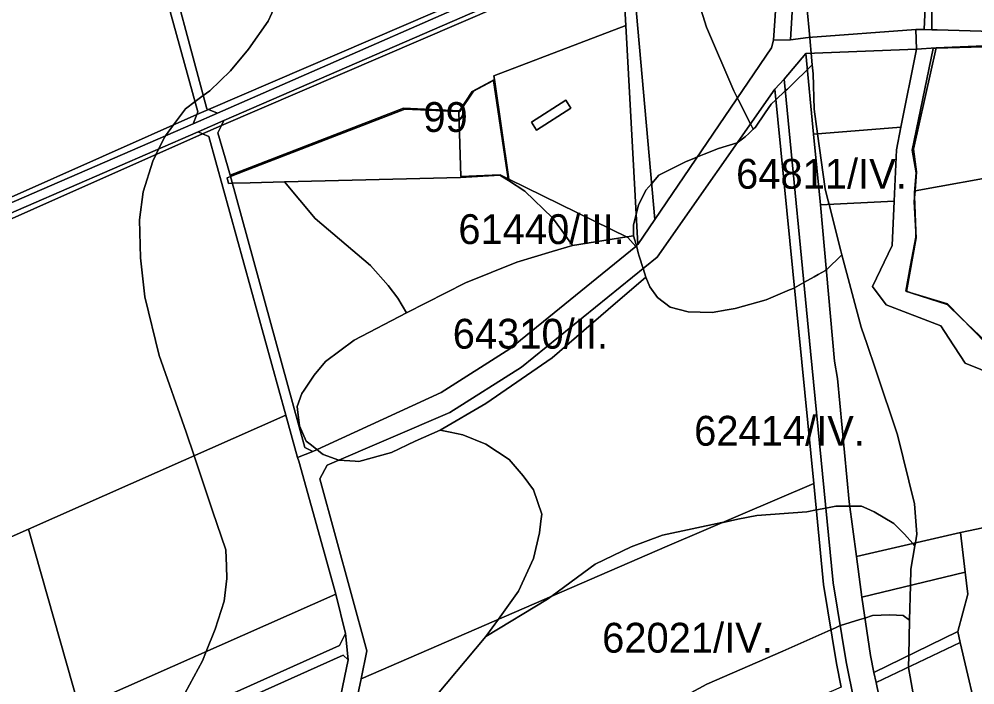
# Model space of a CAD drawing. Extents: x -522079 to -518792, y -1142400 to -1139961.
# Drawn here: x -520985.3 to -520504.8, y -1141508 to -1141173.1 of the extents above; entities that cross this region are included whole.
import ezdxf

# ---------------------------------------------------------------- set-up
doc = ezdxf.new("R2010")
doc.units = 0
for name, color, linetype in [('Bonity', 7, 'Continuous'), ('Hranice parcel', 7, 'Continuous'), ('Parcelní čísla', 7, 'Continuous'), ('Poz předměty', 7, 'Continuous'), ('Vnitřní kresba', 7, 'Continuous'), ('Značky bodu BP', 7, 'Continuous'), ('Značky budov', 7, 'Continuous')]:
    doc.layers.add(name, color=color, linetype=linetype)

msp = doc.modelspace()

# ---------------------------------------------------------------- linework, layer by layer
at = {"layer": 'Bonity'}
msp.add_lwpolyline([(-520879.25, -1141251.61), (-520880.53, -1141246.97), (-520885.33, -1141230.38), (-520883.56, -1141226.59), (-520683.09, -1141140.3), (-520681.18, -1141161.32), (-520680.34, -1141176.38), (-520746.65, -1141201.66), (-520746.38, -1141203.48), (-520757.5, -1141209.45), (-520763.86, -1141219.18), (-520792.12, -1141217.97)], close=True, dxfattribs=at)
at = {"layer": 'Hranice parcel'}
for points in [[(-521027.41, -1141281.92), (-520897.83, -1141225.78), (-520885.55, -1141220.5), (-520708.05, -1141142.54), (-520688.68, -1141134.03), (-520675.02, -1141128.07), (-520610.52, -1141099.9), (-520605.48, -1141096), (-520603.47, -1141094.45), (-520599.33, -1141085.41), (-520601.54, -1141117.64), (-520612.8, -1141110.04), (-520615.64, -1141108.13), (-520683.34, -1141137.56), (-520705.75, -1141147.3), (-520882.39, -1141224.1), (-520895.38, -1141229.74), (-521025.25, -1141286.2)], [(-520594.25, -1141129.86), (-520597.46, -1141183.55), (-520606.07, -1141183.78), (-520601.54, -1141117.64)], [(-520847.36, -1141628.04), (-520819.82, -1141495.44), (-520821.3, -1141482.16), (-520826.14, -1141462.3), (-520844.73, -1141395.54), (-520845.27, -1141393.64), (-520837.57, -1141390.54), (-520773.04, -1141360.9), (-520738.6, -1141338.95), (-520675.31, -1141287.41), (-520674.18, -1141286.49), (-520665.65, -1141273.94), (-520607.02, -1141187.64), (-520606.07, -1141183.78), (-520597.46, -1141183.55), (-520588.63, -1141182.42), (-520534.49, -1141178.34), (-520534.17, -1141188.18), (-520589.77, -1141190.43), (-520600.66, -1141203.4), (-520605.35, -1141208.42), (-520664.52, -1141292.81), (-520732.72, -1141348.25), (-520768.7, -1141371.01), (-520830.45, -1141397.51), (-520834.09, -1141404.31), (-520810.51, -1141490.93), (-520813.35, -1141504.9), (-520838.97, -1141624.77)], [(-520500.08, -1141186.63), (-520524.27, -1141187.6), (-520534.17, -1141188.18), (-520534.49, -1141178.34), (-520530.26, -1141178.39), (-520526.48, -1141178.44), (-520523.78, -1141178.47), (-520440.68, -1141181.04)], [(-520572, -1141509.22), (-520574.39, -1141497.17), (-520580.93, -1141457.51), (-520585.72, -1141406.64), (-520605.35, -1141208.42), (-520600.66, -1141203.4), (-520587.35, -1141340.09), (-520576, -1141456.7), (-520569.46, -1141496.36), (-520561.68, -1141535.49)]]:
    msp.add_lwpolyline(points, dxfattribs=at)
for points in [[(-520890.16, -1141218.54), (-520727.16, -1141148.38), (-520686.99, -1141131.09), (-520688.68, -1141134.03), (-520708.05, -1141142.54), (-520885.55, -1141220.5)], [(-520683.34, -1141137.56), (-520683.09, -1141140.3), (-520883.56, -1141226.59), (-520882.39, -1141224.1), (-520705.75, -1141147.3)], [(-520683.09, -1141140.3), (-520677.78, -1141138.02), (-520665.65, -1141273.94), (-520674.18, -1141286.49), (-520680.34, -1141176.38), (-520681.18, -1141161.32)], [(-520535.7, -1141238.47), (-520524.27, -1141187.6), (-520500.08, -1141186.63), (-520488.31, -1141251.1), (-520534.84, -1141259.42), (-520534.05, -1141249.88)], [(-520743.39, -1141251.48), (-520763.26, -1141252.34), (-520764.2, -1141219.7), (-520763.86, -1141219.18), (-520757.5, -1141209.45), (-520746.38, -1141203.48), (-520739.03, -1141253.62)], [(-520727.76, -1141224.94), (-520710.51, -1141213.9), (-520707.92, -1141217.98), (-520725.18, -1141228.99)], [(-520895.96, -1141221.04), (-520890.16, -1141218.54), (-520885.55, -1141220.5), (-520897.83, -1141225.78)], [(-520895.96, -1141221.04), (-520897.83, -1141225.78), (-521027.41, -1141281.92), (-521037.84, -1141286.59), (-521038.45, -1141284.46)], [(-520882.39, -1141224.1), (-520883.56, -1141226.59), (-520893.13, -1141230.74), (-520895.38, -1141229.74)], [(-520837.57, -1141390.54), (-520845.27, -1141393.64), (-520851.22, -1141372.34), (-520889.86, -1141232.13), (-520893.13, -1141230.74), (-520883.56, -1141226.59), (-520885.33, -1141230.38), (-520880.53, -1141246.97), (-520879.25, -1141251.61), (-520841.7, -1141388.53)], [(-520893.13, -1141230.74), (-521147.68, -1141344.03), (-521146.08, -1141340.6), (-521025.25, -1141286.2), (-520895.38, -1141229.74)]]:
    msp.add_lwpolyline(points, close=True, dxfattribs=at)
at = {"layer": 'Parcelní čísla'}
for points in [[(-520948.18, -1141008.97), (-520939.75, -1141038.42), (-520928.14, -1141079.25), (-520914.59, -1141129.89), (-520890.98, -1141218.17), (-520890.16, -1141218.54), (-520895.96, -1141221.04), (-520895.4, -1141219.71), (-520927.66, -1141102.94), (-520964.29, -1140970.32), (-520970.5, -1140967.09), (-520956.56, -1140961.79), (-520959.78, -1140968.46), (-520955.5, -1140983.4), (-520952.2, -1140994.93)], [(-520895.4, -1141219.71), (-520895.96, -1141221.04), (-521038.45, -1141284.46), (-521072.62, -1141164.33), (-521112.83, -1141022.98), (-521082.18, -1141009.47), (-521026.59, -1140987.63), (-520970.5, -1140967.09), (-520964.29, -1140970.32), (-520927.66, -1141102.94)], [(-520914.59, -1141129.89), (-520847.24, -1141100.33), (-520846.14, -1141104.23), (-520733.88, -1141082.24), (-520727.16, -1141148.38), (-520890.16, -1141218.54), (-520890.98, -1141218.17)], [(-520851.22, -1141372.34), (-520980.65, -1141429.68), (-521109.72, -1141486.85), (-521149.23, -1141347.36), (-521147.68, -1141344.03), (-520893.13, -1141230.74), (-520889.86, -1141232.13)], [(-520980.65, -1141429.68), (-520851.22, -1141372.34), (-520845.27, -1141393.64), (-520844.73, -1141395.54), (-520826.14, -1141462.3), (-520955.18, -1141519.6)], [(-520659.49, -1141438.15), (-520585.72, -1141406.64), (-520580.93, -1141457.51), (-520574.39, -1141497.17), (-520572, -1141509.22), (-520635.55, -1141536.73), (-520726.9, -1141576.27), (-520838.97, -1141624.77), (-520813.35, -1141504.9)], [(-520980.65, -1141429.68), (-520955.18, -1141519.6), (-521084.21, -1141576.91), (-521109.72, -1141486.85)], [(-520821.3, -1141482.16), (-520824.28, -1141488.21), (-520974.97, -1141555.99), (-521072.78, -1141598.79), (-521078.78, -1141596.05), (-521084.21, -1141576.91), (-520955.18, -1141519.6), (-520826.14, -1141462.3)], [(-520819.82, -1141495.44), (-520822.47, -1141493.04), (-520972.97, -1141560.63), (-521070.28, -1141603.2), (-521076.03, -1141605.72), (-521077.42, -1141600.82), (-521072.78, -1141598.79), (-520974.97, -1141555.99), (-520824.28, -1141488.21), (-520821.3, -1141482.16)], [(-520822.47, -1141493.04), (-520819.82, -1141495.44), (-520847.36, -1141628.04), (-520954.68, -1141675.43), (-521044.98, -1141715.3), (-521058.67, -1141667), (-521074.66, -1141610.52), (-521070.28, -1141603.2), (-520972.97, -1141560.63)]]:
    msp.add_lwpolyline(points, close=True, dxfattribs=at)
at = {"layer": 'Poz předměty'}
for points in [[(-520597.46, -1141183.55), (-520594.25, -1141129.86), (-520552.98, -1141119.42), (-520553, -1141122.43), (-520562.26, -1141141.67), (-520551.87, -1141154.33), (-520536.94, -1141152.14), (-520531.44, -1141160.96), (-520529.73, -1141167.05), (-520530.26, -1141178.39), (-520534.49, -1141178.34), (-520588.63, -1141182.42)], [(-520432.59, -1141179.7), (-520440.68, -1141181.04), (-520523.78, -1141178.47), (-520526.48, -1141178.44), (-520526.38, -1141166.45), (-520421.91, -1141158.52), (-520408.18, -1141157.48), (-520425.27, -1141175.41)], [(-520679.28, -1141282.96), (-520739.03, -1141253.62), (-520746.38, -1141203.48), (-520746.65, -1141201.66), (-520680.34, -1141176.38), (-520674.18, -1141286.49), (-520675.31, -1141287.41)], [(-520589.77, -1141190.43), (-520534.17, -1141188.18), (-520541.94, -1141227.47), (-520585.84, -1141231.02)], [(-520727.76, -1141224.94), (-520725.18, -1141228.99), (-520707.92, -1141217.98), (-520710.51, -1141213.9)], [(-520585.84, -1141231.02), (-520541.94, -1141227.47), (-520544.19, -1141238.83), (-520545.37, -1141264.63), (-520582.4, -1141266.58)], [(-520534.35, -1141283.17), (-520535.3, -1141264.93), (-520534.84, -1141259.42), (-520488.31, -1141251.1), (-520469.72, -1141352.88), (-520465.21, -1141361), (-520463.1, -1141373.93), (-520471.76, -1141351.9), (-520499.06, -1141336.21), (-520518.61, -1141316.36), (-520539.2, -1141310.09)], [(-520474.23, -1141423.42), (-520512.06, -1141431.3), (-520564.35, -1141443.41), (-520567.96, -1141415.92), (-520573.91, -1141353.97), (-520575.29, -1141345.21), (-520582.4, -1141266.58), (-520545.37, -1141264.63), (-520546.39, -1141287.04), (-520556.25, -1141307.68), (-520549.32, -1141316.76), (-520521.95, -1141327.46), (-520517.94, -1141333.55), (-520509.58, -1141346.13), (-520479.06, -1141358.55)], [(-520509.69, -1141451.35), (-520561.66, -1141463.92), (-520564.35, -1141443.41), (-520512.06, -1141431.3)], [(-520508.38, -1141462.38), (-520513.39, -1141481.08), (-520555.49, -1141501.75), (-520557.24, -1141493.24), (-520561.66, -1141463.92), (-520509.69, -1141451.35)], [(-520513.39, -1141481.08), (-520512.09, -1141486.67), (-520554.45, -1141506.79), (-520555.49, -1141501.75)], [(-520549.23, -1141532.17), (-520554.45, -1141506.79), (-520512.09, -1141486.67), (-520501.99, -1141530.25), (-520478.09, -1141540.57), (-520469.99, -1141514.94), (-520451.9, -1141513.8), (-520438.57, -1141562.32), (-520457.06, -1141558.71), (-520539.75, -1141570.9)]]:
    msp.add_lwpolyline(points, close=True, dxfattribs=at)
msp.add_lwpolyline([(-520561.68, -1141535.49), (-520569.46, -1141496.36), (-520576, -1141456.7), (-520587.35, -1141340.09), (-520600.66, -1141203.4), (-520589.77, -1141190.43), (-520585.84, -1141231.02), (-520582.4, -1141266.58), (-520575.29, -1141345.21), (-520573.91, -1141353.97), (-520567.96, -1141415.92), (-520564.35, -1141443.41), (-520561.66, -1141463.92), (-520557.24, -1141493.24), (-520555.49, -1141501.75), (-520554.45, -1141506.79), (-520549.23, -1141532.17)], dxfattribs=at)
at = {"layer": 'Vnitřní kresba'}
for points in [[(-520526.38, -1141166.45), (-520526.48, -1141178.44), (-520530.26, -1141178.39), (-520529.73, -1141167.05)], [(-520479.06, -1141358.55), (-520509.58, -1141346.13), (-520517.94, -1141333.55), (-520521.95, -1141327.46), (-520549.32, -1141316.76), (-520556.25, -1141307.68), (-520546.39, -1141287.04), (-520545.37, -1141264.63), (-520544.19, -1141238.83), (-520541.94, -1141227.47), (-520534.17, -1141188.18), (-520524.27, -1141187.6), (-520535.7, -1141238.47), (-520534.05, -1141249.88), (-520534.84, -1141259.42), (-520535.3, -1141264.93), (-520534.35, -1141283.17), (-520539.2, -1141310.09), (-520518.61, -1141316.36), (-520499.06, -1141336.21)], [(-520501.99, -1141530.25), (-520512.09, -1141486.67), (-520513.39, -1141481.08), (-520508.38, -1141462.38), (-520509.69, -1141451.35), (-520512.06, -1141431.3), (-520474.23, -1141423.42)]]:
    msp.add_lwpolyline(points, dxfattribs=at)
at = {"layer": 'Značky bodu BP'}
for points in [[(-520906.25, -1141519.97), (-520893.11, -1141495.88), (-520891.25, -1141491.21), (-520886.77, -1141479.98), (-520882.24, -1141465.89), (-520880.88, -1141454.53), (-520881.08, -1141448.32), (-520881.34, -1141439.99), (-520888.13, -1141420.45), (-520897.33, -1141392.76), (-520901.27, -1141380.91), (-520914.86, -1141342.28), (-520922.11, -1141312.75), (-520924.37, -1141293.2), (-520924.82, -1141274.12), (-520923.01, -1141260.03), (-520918.03, -1141244.58), (-520916.34, -1141241.07), (-520915, -1141238.27), (-520912.14, -1141232.31), (-520911.78, -1141231.82), (-520907.65, -1141226.24), (-520901.72, -1141218.22), (-520896.82, -1141214.58), (-520892.75, -1141211.56), (-520889.49, -1141209.13), (-520879.07, -1141199.13), (-520870.01, -1141188.23), (-520860.04, -1141174.14), (-520854.61, -1141161.87)], [(-520854.61, -1141161.87), (-520860.04, -1141174.14), (-520870.01, -1141188.23), (-520879.07, -1141199.13), (-520889.49, -1141209.13), (-520892.75, -1141211.56), (-520896.82, -1141214.58), (-520901.72, -1141218.22), (-520907.65, -1141226.24), (-520911.78, -1141231.82), (-520912.14, -1141232.31), (-520915, -1141238.27), (-520916.34, -1141241.07), (-520918.03, -1141244.58), (-520923.01, -1141260.03), (-520924.82, -1141274.12), (-520924.37, -1141293.2), (-520922.11, -1141312.75), (-520914.86, -1141342.28), (-520901.27, -1141380.91), (-520897.33, -1141392.76), (-520888.13, -1141420.45), (-520881.34, -1141439.99), (-520881.08, -1141448.32), (-520880.88, -1141454.53), (-520882.24, -1141465.89), (-520886.77, -1141479.98), (-520891.25, -1141491.21), (-520893.11, -1141495.88), (-520906.25, -1141519.97)], [(-520644.35, -1141162.05), (-520639.78, -1141177.21), (-520625.97, -1141209.18), (-520624.13, -1141212.83), (-520623.62, -1141213.83), (-520617.56, -1141225.84), (-520616.21, -1141228.52), (-520618.44, -1141230.62), (-520620.26, -1141232.34), (-520624.21, -1141235.31), (-520624.35, -1141235.42), (-520633.7, -1141238.2), (-520640.88, -1141241.06), (-520644.21, -1141242.38), (-520646.99, -1141243.49), (-520649.92, -1141244.66), (-520663.65, -1141251.69), (-520667.27, -1141255.8), (-520670.23, -1141259.17), (-520673.89, -1141266.75), (-520675.03, -1141271.22), (-520676.44, -1141276.73), (-520676.44, -1141282.14), (-520679.84, -1141282.68), (-520707.07, -1141287), (-520712.45, -1141279.5), (-520717.11, -1141273), (-520731.06, -1141259.66), (-520739.34, -1141254.29), (-520739.47, -1141253.4), (-520746.78, -1141204), (-520756.85, -1141209.44), (-520763.8, -1141219.61), (-520764.13, -1141219.59), (-520791.31, -1141218.35), (-520871.38, -1141249.26), (-520879.08, -1141252.24), (-520880.78, -1141252.89), (-520880, -1141255.73), (-520878.14, -1141255.68), (-520869.12, -1141255.45), (-520851.89, -1141255.02), (-520836.39, -1141273.44), (-520808.7, -1141297.06), (-520799.76, -1141307.12), (-520794.96, -1141313.47), (-520790.6, -1141320.91), (-520816.82, -1141334.59), (-520831.31, -1141345.42), (-520837, -1141352.26), (-520842.08, -1141359.69), (-520843.25, -1141361.39), (-520845.52, -1141367.94), (-520845.35, -1141369.42), (-520844.38, -1141377.63), (-520840.97, -1141385.33), (-520838.35, -1141387.44), (-520835.61, -1141389.64), (-520834.78, -1141390.3), (-520833.74, -1141391.13), (-520832.45, -1141392.17), (-520824.58, -1141394.99), (-520824.49, -1141395.02), (-520816.33, -1141395.49), (-520814.55, -1141395.59), (-520798.06, -1141391.03), (-520786.13, -1141385.33), (-520773.63, -1141379.92), (-520768.66, -1141380.95), (-520762.28, -1141382.28), (-520750.59, -1141386.97), (-520738.9, -1141394.59), (-520731.89, -1141402.8), (-520726.63, -1141409.84), (-520722.54, -1141422.15), (-520722.98, -1141425.69), (-520723.7, -1141431.53), (-520726.63, -1141444.43), (-520734.22, -1141460.84), (-520744.32, -1141474.95), (-520750.59, -1141483.71), (-520775.72, -1141513.61)], [(-520589.2, -1141166.56), (-520587.79, -1141182.35), (-520587.59, -1141184.62), (-520587.08, -1141190.32), (-520586.56, -1141196.12), (-520587.8, -1141197.35), (-520588.98, -1141198.53), (-520595.57, -1141205.08), (-520599.04, -1141208.31), (-520599.49, -1141208.72), (-520600.09, -1141209.27), (-520604.83, -1141213.68), (-520607.26, -1141215.93), (-520610.17, -1141220.2), (-520615.14, -1141227.51), (-520616.21, -1141228.52), (-520617.56, -1141225.84), (-520623.62, -1141213.83), (-520624.13, -1141212.83), (-520625.97, -1141209.18), (-520639.78, -1141177.21), (-520644.35, -1141162.05)], [(-520533.32, -1141526.62), (-520538.18, -1141499.21), (-520538.17, -1141499.06), (-520538.02, -1141493.17), (-520537.57, -1141475.45), (-520537.16, -1141457.99), (-520536.96, -1141449.86), (-520534.94, -1141438.08), (-520534.67, -1141436.53), (-520533.93, -1141432.19), (-520535.14, -1141416.96), (-520543.64, -1141382.23), (-520554.4, -1141350.22), (-520559.25, -1141335.8), (-520560.23, -1141332.87), (-520561.86, -1141328.01), (-520571.65, -1141291.62), (-520572.19, -1141289.63), (-520578.1, -1141266.35), (-520579.04, -1141262.66), (-520580.09, -1141258.56), (-520583.85, -1141230.86), (-520585.55, -1141218.35), (-520586.16, -1141200.68), (-520586.56, -1141196.12), (-520587.08, -1141190.32), (-520587.59, -1141184.62), (-520587.79, -1141182.35), (-520589.2, -1141166.56)], [(-520500.85, -1141187.11), (-520524.31, -1141187.79), (-520525.78, -1141187.83), (-520536.29, -1141238.97), (-520534.37, -1141250.38), (-520535.13, -1141260.34), (-520535.07, -1141262.19), (-520534.53, -1141279.71), (-520534.53, -1141279.78), (-520534.44, -1141282.78), (-520537.07, -1141296.8), (-520539.53, -1141309.92), (-520539.19, -1141310.03), (-520536.52, -1141310.91), (-520518.63, -1141316.73), (-520511.59, -1141323.48), (-520499.45, -1141335.14)], [(-520499.45, -1141335.14), (-520511.59, -1141323.48), (-520518.63, -1141316.73), (-520536.52, -1141310.91), (-520539.19, -1141310.03), (-520539.53, -1141309.92), (-520537.07, -1141296.8), (-520534.44, -1141282.78), (-520534.53, -1141279.78), (-520534.53, -1141279.71), (-520535.07, -1141262.19), (-520535.13, -1141260.34), (-520534.37, -1141250.38), (-520536.29, -1141238.97), (-520525.78, -1141187.83), (-520524.31, -1141187.79), (-520500.85, -1141187.11)], [(-520775.72, -1141513.61), (-520750.59, -1141483.71), (-520719.61, -1141464.95), (-520717.23, -1141463.2), (-520695.65, -1141447.36), (-520677.53, -1141438.57), (-520661.75, -1141432.7), (-520631.92, -1141426.37), (-520631.36, -1141426.25), (-520623.91, -1141424.71), (-520614.41, -1141422.74), (-520589.28, -1141420.98), (-520584.46, -1141420.01), (-520579.66, -1141419.04), (-520574.67, -1141418.04), (-520571.52, -1141418.04), (-520567.68, -1141418.04), (-520561.82, -1141418.04), (-520559.11, -1141419.28), (-520555.39, -1141420.98), (-520545.45, -1141426.84), (-520540.19, -1141432.11), (-520536.02, -1141436.85), (-520534.94, -1141438.08), (-520536.96, -1141449.86), (-520537.16, -1141457.99), (-520537.57, -1141475.45), (-520540.8, -1141473.17), (-520547.46, -1141472.82), (-520556.21, -1141473.17), (-520560.09, -1141474.36), (-520562.57, -1141475.11), (-520572.31, -1141478.09), (-520572.46, -1141478.16), (-520574.86, -1141479.23), (-520577.18, -1141480.26), (-520601.37, -1141491.08), (-520639.54, -1141507.59), (-520673.15, -1141525.85)], [(-520673.15, -1141525.85), (-520639.54, -1141507.59), (-520601.37, -1141491.08), (-520577.18, -1141480.26), (-520574.86, -1141479.23), (-520572.46, -1141478.16), (-520572.31, -1141478.09), (-520562.57, -1141475.11), (-520560.09, -1141474.36), (-520556.21, -1141473.17), (-520547.46, -1141472.82), (-520540.8, -1141473.17), (-520537.57, -1141475.45), (-520538.02, -1141493.17), (-520538.17, -1141499.06), (-520538.18, -1141499.21), (-520533.32, -1141526.62)]]:
    msp.add_lwpolyline(points, dxfattribs=at)
for points in [[(-520629.39, -1141319.4), (-520636.91, -1141320.73), (-520648.9, -1141320.43), (-520657.95, -1141318.09), (-520664.38, -1141313.1), (-520668.18, -1141307.83), (-520670.19, -1141302.95), (-520671.61, -1141298.57), (-520673.6, -1141292.41), (-520674, -1141290.74), (-520674.02, -1141290.67), (-520674.36, -1141289.21), (-520674.87, -1141287.05), (-520675.02, -1141286.42), (-520676.44, -1141282.14), (-520676.44, -1141276.73), (-520675.03, -1141271.22), (-520673.89, -1141266.75), (-520670.23, -1141259.17), (-520667.27, -1141255.8), (-520663.65, -1141251.69), (-520649.92, -1141244.66), (-520646.99, -1141243.49), (-520644.21, -1141242.38), (-520640.88, -1141241.06), (-520633.7, -1141238.2), (-520624.35, -1141235.42), (-520624.21, -1141235.31), (-520620.26, -1141232.34), (-520618.44, -1141230.62), (-520616.21, -1141228.52), (-520615.14, -1141227.51), (-520610.17, -1141220.2), (-520607.26, -1141215.93), (-520604.83, -1141213.68), (-520600.09, -1141209.27), (-520599.49, -1141208.72), (-520599.04, -1141208.31), (-520595.57, -1141205.08), (-520588.98, -1141198.53), (-520587.8, -1141197.35), (-520586.56, -1141196.12), (-520586.16, -1141200.68), (-520585.55, -1141218.35), (-520583.85, -1141230.86), (-520580.09, -1141258.56), (-520579.04, -1141262.66), (-520578.1, -1141266.35), (-520572.19, -1141289.63), (-520571.65, -1141291.62), (-520579.45, -1141299.16), (-520579.93, -1141299.62), (-520583.5, -1141301.61), (-520585.65, -1141302.81), (-520590.71, -1141305.62), (-520595.46, -1141308.27), (-520595.71, -1141308.41), (-520598.01, -1141309.37), (-520609.74, -1141314.27), (-520625.23, -1141318.67)], [(-520746.78, -1141204), (-520739.47, -1141253.4), (-520739.34, -1141254.29), (-520743.07, -1141251.94), (-520743.59, -1141251.61), (-520763.46, -1141252.81), (-520851.89, -1141255.02), (-520869.12, -1141255.45), (-520878.14, -1141255.68), (-520880, -1141255.73), (-520880.78, -1141252.89), (-520879.08, -1141252.24), (-520871.38, -1141249.26), (-520791.31, -1141218.35), (-520764.13, -1141219.59), (-520763.8, -1141219.61), (-520756.85, -1141209.44)], [(-520739.34, -1141254.29), (-520731.06, -1141259.66), (-520717.11, -1141273), (-520712.45, -1141279.5), (-520707.07, -1141287), (-520717.31, -1141290.05), (-520734.99, -1141295.31), (-520760.94, -1141305.81), (-520790.6, -1141320.91), (-520794.96, -1141313.47), (-520799.76, -1141307.12), (-520808.7, -1141297.06), (-520836.39, -1141273.44), (-520851.89, -1141255.02), (-520763.46, -1141252.81), (-520743.59, -1141251.61), (-520743.07, -1141251.94)], [(-520670.19, -1141302.95), (-520689.23, -1141319.2), (-520717.36, -1141343.43), (-520750.61, -1141366.52), (-520773.63, -1141379.92), (-520786.13, -1141385.33), (-520798.06, -1141391.03), (-520814.55, -1141395.59), (-520816.33, -1141395.49), (-520824.49, -1141395.02), (-520824.58, -1141394.99), (-520832.45, -1141392.17), (-520833.74, -1141391.13), (-520834.78, -1141390.3), (-520835.61, -1141389.64), (-520838.35, -1141387.44), (-520840.97, -1141385.33), (-520844.38, -1141377.63), (-520845.35, -1141369.42), (-520845.52, -1141367.94), (-520843.25, -1141361.39), (-520842.08, -1141359.69), (-520837, -1141352.26), (-520831.31, -1141345.42), (-520816.82, -1141334.59), (-520790.6, -1141320.91), (-520760.94, -1141305.81), (-520734.99, -1141295.31), (-520717.31, -1141290.05), (-520707.07, -1141287), (-520679.84, -1141282.68), (-520676.44, -1141282.14), (-520675.02, -1141286.42), (-520674.87, -1141287.05), (-520674.36, -1141289.21), (-520674.02, -1141290.67), (-520674, -1141290.74), (-520673.6, -1141292.41), (-520671.61, -1141298.57)], [(-520534.94, -1141438.08), (-520536.02, -1141436.85), (-520540.19, -1141432.11), (-520545.45, -1141426.84), (-520555.39, -1141420.98), (-520559.11, -1141419.28), (-520561.82, -1141418.04), (-520567.68, -1141418.04), (-520571.52, -1141418.04), (-520574.67, -1141418.04), (-520579.66, -1141419.04), (-520584.46, -1141420.01), (-520589.28, -1141420.98), (-520614.41, -1141422.74), (-520623.91, -1141424.71), (-520631.36, -1141426.25), (-520631.92, -1141426.37), (-520661.75, -1141432.7), (-520677.53, -1141438.57), (-520695.65, -1141447.36), (-520717.23, -1141463.2), (-520719.61, -1141464.95), (-520750.59, -1141483.71), (-520744.32, -1141474.95), (-520734.22, -1141460.84), (-520726.63, -1141444.43), (-520723.7, -1141431.53), (-520722.98, -1141425.69), (-520722.54, -1141422.15), (-520726.63, -1141409.84), (-520731.89, -1141402.8), (-520738.9, -1141394.59), (-520750.59, -1141386.97), (-520762.28, -1141382.28), (-520768.66, -1141380.95), (-520773.63, -1141379.92), (-520750.61, -1141366.52), (-520717.36, -1141343.43), (-520689.23, -1141319.2), (-520670.19, -1141302.95), (-520668.18, -1141307.83), (-520664.38, -1141313.1), (-520657.95, -1141318.09), (-520648.9, -1141320.43), (-520636.91, -1141320.73), (-520629.39, -1141319.4), (-520625.23, -1141318.67), (-520609.74, -1141314.27), (-520598.01, -1141309.37), (-520595.71, -1141308.41), (-520595.46, -1141308.27), (-520590.71, -1141305.62), (-520585.65, -1141302.81), (-520583.5, -1141301.61), (-520579.93, -1141299.62), (-520579.45, -1141299.16), (-520571.65, -1141291.62), (-520561.86, -1141328.01), (-520560.23, -1141332.87), (-520559.25, -1141335.8), (-520554.4, -1141350.22), (-520543.64, -1141382.23), (-520535.14, -1141416.96), (-520533.93, -1141432.19), (-520534.67, -1141436.53)]]:
    msp.add_lwpolyline(points, close=True, dxfattribs=at)
at = {"layer": 'Značky budov'}
for points in [[(-520607.02, -1141187.64), (-520665.65, -1141273.94), (-520677.78, -1141138.02), (-520612.8, -1141110.04), (-520601.54, -1141117.64), (-520606.07, -1141183.78)], [(-520813.35, -1141504.9), (-520810.51, -1141490.93), (-520834.09, -1141404.31), (-520830.45, -1141397.51), (-520768.7, -1141371.01), (-520732.72, -1141348.25), (-520664.52, -1141292.81), (-520605.35, -1141208.42), (-520585.72, -1141406.64), (-520659.49, -1141438.15)], [(-520837.57, -1141390.54), (-520841.7, -1141388.53), (-520879.25, -1141251.61), (-520792.12, -1141217.97), (-520763.86, -1141219.18), (-520764.2, -1141219.7), (-520763.26, -1141252.34), (-520743.39, -1141251.48), (-520739.03, -1141253.62), (-520679.28, -1141282.96), (-520675.31, -1141287.41), (-520738.6, -1141338.95), (-520773.04, -1141360.9)]]:
    msp.add_lwpolyline(points, close=True, dxfattribs=at)

# ---------------------------------------------------------------- texts
at = {"layer": 'Značky bodu BP'}
for s, rotation, p in [('99', 360, (-520782.05, -1141229.87)), ('64811/IV.', 360, (-520624.84, -1141258.43)), ('61440/III.', 0, (-520764.48, -1141286.26)), ('64310/II.', 360, (-520767.3, -1141338.87)), ('62414/IV.', 360, (-520645.92, -1141387.67)), ('62021/IV.', 0, (-520692.18, -1141491.78))]:
    msp.add_text(s, height=15, rotation=rotation, dxfattribs=at).set_placement(p)

doc.saveas('drawing.dxf')
